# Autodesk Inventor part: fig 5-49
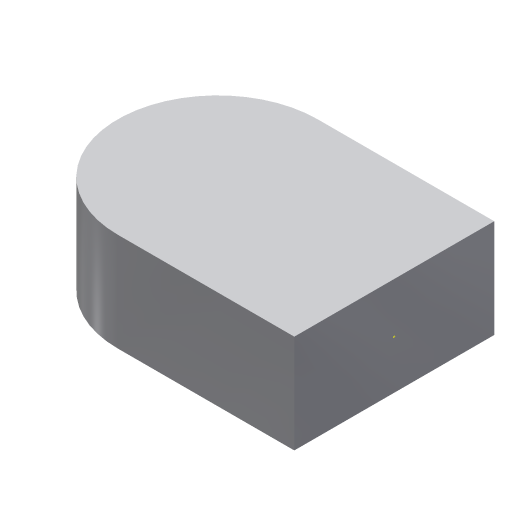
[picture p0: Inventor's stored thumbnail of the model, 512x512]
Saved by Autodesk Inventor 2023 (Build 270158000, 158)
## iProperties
Created: 2010-02
Part Number: fig 5-49
Document SubType Name: Modeling
Designer: CADSoft
Density: 1 g/cm^3
Material: Generic
Appearance: Default
Author: CADSoft
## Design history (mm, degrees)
sketch "Sketch1"
  geometry: L1 (-17.92, 20.292)-(0, 20.292); L2 (0, 20.292)-(0, 0); L3 (0, 0)-(-17.92, 0); A1 r 10.146 centre (-17.92, 10.146) between (-17.92, 20.292) and (-17.92, 0)
  constraints: 6 end point, 2 horizontal, 2 point on circle, 2 tangent, 1 centre point, 1 vertical
extrude "Extrusion1" new body sketch "Sketch1" distance "d0" = 10; taper "d1" = 0 deg
workpoint "Work Point1"
body "Solid1"
